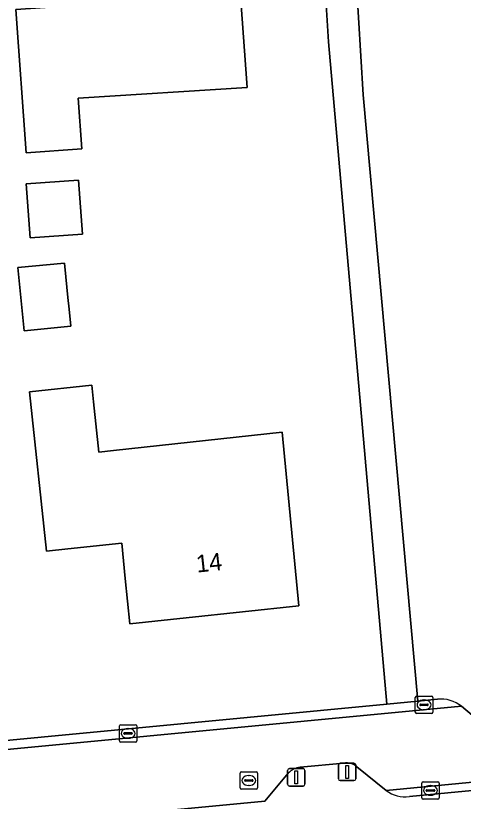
# Model space of a CAD drawing. Extents: x 162661 to 163484, y 380247 to 381230.
# Drawn here: x 163007.21 to 163032.88, y 380282.71 to 380327.82 of the extents above; entities that cross this region are included whole.
import ezdxf

# ---------------------------------------------------------------- set-up
doc = ezdxf.new("R2010")
doc.units = 0
for name, color, linetype in [('IMGEO_Afsluitpaal', 7, 'Continuous'), ('IMGEO_Erf', 7, 'Continuous'), ('IMGEO_Gemengd_bos', 7, 'Continuous'), ('IMGEO_Kolk', 7, 'Continuous'), ('IMGEO_Pand', 7, 'Continuous'), ('IMGEO_Pand_nummerreeks', 7, 'Continuous'), ('IMGEO_Rijbaan_lokaal_gesloten', 7, 'Continuous'), ('IMGEO_Rijbaan_lokaal_open', 7, 'Continuous'), ('IMGEO_Rioolput', 7, 'Continuous'), ('IMGEO_Voetpad_open', 7, 'Continuous')]:
    doc.layers.add(name, color=color, linetype=linetype)

msp = doc.modelspace()

# ---------------------------------------------------------------- linework, layer by layer
at = {"layer": 'IMGEO_Afsluitpaal'}
for p, q in [((163022.906, 380284.583), (163023.696, 380284.583)), ((163023.696, 380284.583), (163022.906, 380284.583)), ((163025.722, 380283.995), (163025.722, 380284.795)), ((163025.722, 380284.795), (163025.722, 380283.995)), ((163025.822, 380284.895), (163026.612, 380284.895)), ((163026.612, 380284.895), (163025.822, 380284.895)), ((163026.712, 380284.795), (163026.712, 380283.995)), ((163026.712, 380283.995), (163026.712, 380284.795)), ((163022.806, 380283.683), (163022.806, 380284.483)), ((163022.806, 380284.483), (163022.806, 380283.683)), ((163023.796, 380284.483), (163023.796, 380283.683)), ((163023.796, 380283.683), (163023.796, 380284.483)), ((163026.612, 380283.895), (163025.822, 380283.895)), ((163025.822, 380283.895), (163026.612, 380283.895)), ((163023.696, 380283.583), (163022.906, 380283.583)), ((163022.906, 380283.583), (163023.696, 380283.583))]:
    msp.add_line(p, q, dxfattribs=at)
for points in [[(163026.142, 380284.77), (163026.292, 380284.77), (163026.292, 380284.02), (163026.142, 380284.02), (163026.142, 380284.77)], [(163023.226, 380284.458), (163023.376, 380284.458), (163023.376, 380283.708), (163023.226, 380283.708), (163023.226, 380284.458)]]:
    msp.add_lwpolyline(points, dxfattribs=at)
for centre, start, end in [((163022.906, 380284.483), 90, 180), ((163022.906, 380284.483), 90, 180), ((163023.696, 380284.483), 0, 90), ((163023.696, 380284.483), 360, 90), ((163025.822, 380284.795), 90, 180), ((163025.822, 380284.795), 90, 180), ((163026.612, 380284.795), 0, 90), ((163026.612, 380284.795), 360, 90), ((163022.906, 380283.683), 180, 270), ((163022.906, 380283.683), 180, 270), ((163023.696, 380283.683), 270, 0), ((163023.696, 380283.683), 270, 0), ((163025.822, 380283.995), 180, 270), ((163025.822, 380283.995), 180, 270), ((163026.612, 380283.995), 270, 0), ((163026.612, 380283.995), 270, 0)]:
    msp.add_arc(centre, 0.1, start, end, dxfattribs=at)
at = {"layer": 'IMGEO_Erf'}
for points in [[(163139.978, 380304.779), (163136.519, 380351.021), (163135.092, 380350.931), (163034.276, 380343.853), (163025.928, 380343.278), (163027.147, 380323.267), (163030.282, 380288.461), (163031.404, 380288.568)], [(163032.785, 380288.167), (163034.368, 380286.84)]]:
    msp.add_lwpolyline(points, dxfattribs=at)
for points in [[(163025.144, 380326.321), (163024.481, 380337.057), (163009.587, 380336.032), (163009.593, 380335.742), (163006.725, 380335.529), (163006.73, 380335.638), (163003.141, 380335.415), (163000, 380335.199), (162936.743, 380330.858), (162941.559, 380279.973), (163028.489, 380288.289)], [(163010.171, 380330.413), (163009.999, 380333.038), (163019.769, 380333.708), (163020.494, 380323.704), (163010.794, 380323.077), (163011.003, 380320.184), (163007.811, 380319.954), (163007.219, 380328.173), (163010.303, 380328.395)], [(163007.817, 380318.159), (163010.814, 380318.375), (163011.037, 380315.276), (163008.041, 380315.06)], [(163007.331, 380313.357), (163010.007, 380313.619), (163010.22, 380311.45), (163010.249, 380311.157), (163010.364, 380309.986), (163007.687, 380309.724)], [(163008.004, 380306.229), (163011.579, 380306.609), (163011.681, 380305.647), (163011.988, 380302.761), (163012.826, 380302.853), (163022.489, 380303.909), (163023.451, 380293.925), (163013.765, 380292.896), (163013.498, 380295.509), (163013.292, 380297.532), (163010.209, 380297.204), (163008.979, 380297.073)]]:
    msp.add_lwpolyline(points, close=True, dxfattribs=at)
msp.add_arc((163031.6, 380286.664), 1.914, 51.7444, 95.8722, dxfattribs=at)
at = {"layer": 'IMGEO_Gemengd_bos'}
for points in [[(163140.672, 380293.543), (163138.153, 380293.364), (163029.791, 380282.976)], [(163026.035, 380284.904), (163023.529, 380284.664)], [(163028.455, 380283.329), (163026.78, 380284.687)], [(163022.836, 380284.315), (163021.508, 380282.709)]]:
    msp.add_lwpolyline(points, dxfattribs=at)
for centre, radius, start, end in [((163023.635, 380283.591), 1.078, 95.6384, 137.8219), ((163026.175, 380283.997), 0.918, 48.7473, 98.7737), ((163029.554, 380284.783), 1.822, 232.9158, 277.4831)]:
    msp.add_arc(centre, radius, start, end, dxfattribs=at)
at = {"layer": 'IMGEO_Kolk'}
for p, q in [((163030.131, 380287.822), (163030.131, 380288.674)), ((163030.206, 380288.748), (163031.058, 380288.748)), ((163031.132, 380288.674), (163031.132, 380287.822)), ((163030.39, 380288.242), (163030.39, 380288.254)), ((163030.828, 380288.205), (163030.43, 380288.205)), ((163030.433, 380288.291), (163030.831, 380288.291)), ((163030.619, 380288.528), (163030.644, 380288.528)), ((163030.874, 380288.254), (163030.874, 380288.242)), ((163031.058, 380287.748), (163030.206, 380287.748)), ((163030.642, 380287.968), (163030.617, 380287.968)), ((163013.157, 380286.181), (163013.157, 380287.033)), ((163013.232, 380287.107), (163014.084, 380287.107)), ((163013.645, 380286.887), (163013.67, 380286.887)), ((163014.158, 380287.033), (163014.158, 380286.181)), ((163013.416, 380286.601), (163013.416, 380286.613)), ((163013.854, 380286.564), (163013.456, 380286.564)), ((163013.459, 380286.65), (163013.857, 380286.65)), ((163013.668, 380286.327), (163013.643, 380286.327)), ((163013.9, 380286.613), (163013.9, 380286.601)), ((163014.084, 380286.107), (163013.232, 380286.107)), ((163030.498, 380282.907), (163030.498, 380283.759)), ((163030.573, 380283.833), (163031.425, 380283.833)), ((163031.499, 380283.759), (163031.499, 380282.907)), ((163030.757, 380283.327), (163030.757, 380283.339)), ((163031.195, 380283.29), (163030.797, 380283.29)), ((163030.8, 380283.376), (163031.198, 380283.376)), ((163030.986, 380283.613), (163031.011, 380283.613)), ((163031.241, 380283.339), (163031.241, 380283.327)), ((163031.425, 380282.833), (163030.573, 380282.833)), ((163031.009, 380283.053), (163030.984, 380283.053))]:
    msp.add_line(p, q, dxfattribs=at)
for points in [[(163030.131, 380287.822), (163030.131, 380288.674)], [(163030.206, 380288.748), (163031.058, 380288.748)], [(163031.132, 380288.674), (163031.132, 380287.822)], [(163031.058, 380287.748), (163030.206, 380287.748)], [(163013.157, 380286.181), (163013.157, 380287.033)], [(163013.232, 380287.107), (163014.084, 380287.107)], [(163014.158, 380287.033), (163014.158, 380286.181)], [(163014.084, 380286.107), (163013.232, 380286.107)], [(163030.498, 380282.907), (163030.498, 380283.759)], [(163030.573, 380283.833), (163031.425, 380283.833)], [(163031.499, 380283.759), (163031.499, 380282.907)], [(163031.425, 380282.833), (163030.573, 380282.833)]]:
    msp.add_lwpolyline(points, dxfattribs=at)
for centre, radius, start, end in [((163030.208, 380288.672), 0.0765, 91.552, 178.448), ((163030.208, 380288.672), 0.0765, 91.552, 178.448), ((163031.056, 380288.672), 0.0765, 1.552, 88.448), ((163031.056, 380288.672), 0.0765, 1.552, 88.448), ((163030.43, 380288.251), 0.0403, 85.8775, 175.7526), ((163030.427, 380288.241), 0.0366, 178.938, 274.7102), ((163030.831, 380288.248), 0.043, 264.8664, 352.4533), ((163030.835, 380288.253), 0.0386, 1.7309, 96.639), ((163030.208, 380287.824), 0.0765, 181.552, 268.448), ((163030.208, 380287.824), 0.0765, 181.552, 268.448), ((163031.056, 380287.824), 0.0765, 271.552, 358.448), ((163031.056, 380287.824), 0.0765, 271.552, 358.448), ((163013.234, 380287.031), 0.0765, 91.552, 178.448), ((163013.234, 380287.031), 0.0765, 91.552, 178.448), ((163014.082, 380287.031), 0.0765, 1.552, 88.448), ((163014.082, 380287.031), 0.0765, 1.552, 88.448), ((163013.456, 380286.61), 0.0403, 85.8775, 175.7526), ((163013.453, 380286.6), 0.0366, 178.938, 274.7102), ((163013.857, 380286.607), 0.043, 264.8664, 352.4533), ((163013.861, 380286.612), 0.0386, 1.7309, 96.639), ((163013.234, 380286.183), 0.0765, 181.552, 268.448), ((163013.234, 380286.183), 0.0765, 181.552, 268.448), ((163014.082, 380286.183), 0.0765, 271.552, 358.448), ((163014.082, 380286.183), 0.0765, 271.552, 358.448), ((163030.575, 380283.757), 0.0765, 91.552, 178.448), ((163030.575, 380283.757), 0.0765, 91.552, 178.448), ((163031.423, 380283.757), 0.0765, 1.552, 88.448), ((163031.423, 380283.757), 0.0765, 1.552, 88.448), ((163030.797, 380283.336), 0.0403, 85.8775, 175.7526), ((163030.794, 380283.326), 0.0366, 178.938, 274.7102), ((163031.198, 380283.333), 0.043, 264.8664, 352.4533), ((163031.202, 380283.338), 0.0386, 1.7309, 96.639), ((163030.575, 380282.909), 0.0765, 181.552, 268.448), ((163030.575, 380282.909), 0.0765, 181.552, 268.448), ((163031.423, 380282.909), 0.0765, 271.552, 358.448), ((163031.423, 380282.909), 0.0765, 271.552, 358.448)]:
    msp.add_arc(centre, radius, start, end, dxfattribs=at)
for centre, major_axis, ratio, start_param, end_param in [((163030.618, 380288.248), (-0.387, 0.002), 0.722429, 4.712389, 7.853982), ((163030.643, 380288.248), (-0.39, 0.002), 0.717154, 1.570796, 4.712389), ((163013.644, 380286.607), (-0.387, 0.002), 0.722429, 4.712389, 7.853982), ((163013.669, 380286.607), (-0.39, 0.002), 0.717154, 1.570796, 4.712389), ((163030.985, 380283.333), (-0.387, 0.002), 0.722429, 4.712389, 7.853982), ((163031.01, 380283.333), (-0.39, 0.002), 0.717154, 1.570796, 4.712389)]:
    msp.add_ellipse(centre, major_axis=major_axis, ratio=ratio, start_param=start_param, end_param=end_param, dxfattribs=at)
at = {"layer": 'IMGEO_Pand'}
for points in [[(163010.171, 380330.413), (163010.303, 380328.395), (163007.219, 380328.173), (163007.811, 380319.954), (163011.003, 380320.184), (163010.794, 380323.077), (163020.494, 380323.704), (163019.769, 380333.708), (163009.999, 380333.038)], [(163007.817, 380318.159), (163008.041, 380315.06), (163011.037, 380315.276), (163010.814, 380318.375)], [(163007.331, 380313.357), (163007.687, 380309.724), (163010.364, 380309.986), (163010.249, 380311.157), (163010.22, 380311.45), (163010.007, 380313.619)], [(163022.489, 380303.909), (163012.826, 380302.853), (163011.988, 380302.761), (163011.681, 380305.647), (163011.579, 380306.609), (163008.004, 380306.229), (163008.979, 380297.073), (163010.209, 380297.204), (163013.292, 380297.532), (163013.498, 380295.509), (163013.765, 380292.896), (163023.451, 380293.925)]]:
    msp.add_lwpolyline(points, close=True, dxfattribs=at)
at = {"layer": 'IMGEO_Rijbaan_lokaal_gesloten'}
for points in [[(163026.78, 380284.687), (163028.455, 380283.329), (163112.592, 380291.447), (163140.62, 380294.079)], [(163034.368, 380286.84), (163032.785, 380288.167), (162941.711, 380279.483), (162940.195, 380274.962), (163021.508, 380282.709)], [(163023.529, 380284.664), (163026.035, 380284.904)], [(163021.508, 380282.709), (163022.836, 380284.315)]]:
    msp.add_lwpolyline(points, dxfattribs=at)
for centre, radius, start, end in [((163023.635, 380283.591), 1.078, 95.6384, 137.8219), ((163026.175, 380283.997), 0.918, 48.7473, 98.7737)]:
    msp.add_arc(centre, radius, start, end, dxfattribs=at)
at = {"layer": 'IMGEO_Rijbaan_lokaal_open'}
for points in [[(163140.62, 380294.079), (163112.592, 380291.447), (163028.455, 380283.329)], [(163029.791, 380282.976), (163138.153, 380293.364)], [(163031.404, 380288.568), (163030.282, 380288.461), (163028.489, 380288.289), (162941.559, 380279.973), (162941.711, 380279.483), (163032.785, 380288.167)], [(163021.508, 380282.709), (162940.195, 380274.962)]]:
    msp.add_lwpolyline(points, dxfattribs=at)
for centre, radius, start, end in [((163031.6, 380286.664), 1.914, 51.7444, 95.8722), ((163029.554, 380284.783), 1.822, 232.9158, 277.4831)]:
    msp.add_arc(centre, radius, start, end, dxfattribs=at)
at = {"layer": 'IMGEO_Rioolput'}
for p, q in [((163020.082, 380283.476), (163020.082, 380284.328)), ((163020.157, 380284.402), (163021.009, 380284.402)), ((163020.57, 380284.182), (163020.595, 380284.182)), ((163021.083, 380284.328), (163021.083, 380283.476)), ((163020.341, 380283.896), (163020.341, 380283.908)), ((163020.779, 380283.859), (163020.381, 380283.859)), ((163020.384, 380283.945), (163020.782, 380283.945)), ((163020.593, 380283.622), (163020.568, 380283.622)), ((163020.825, 380283.908), (163020.825, 380283.896)), ((163021.009, 380283.402), (163020.157, 380283.402))]:
    msp.add_line(p, q, dxfattribs=at)
for points in [[(163020.082, 380283.476), (163020.082, 380284.328)], [(163020.157, 380284.402), (163021.009, 380284.402)], [(163021.083, 380284.328), (163021.083, 380283.476)], [(163021.009, 380283.402), (163020.157, 380283.402)]]:
    msp.add_lwpolyline(points, dxfattribs=at)
for centre, radius, start, end in [((163020.159, 380284.326), 0.0765, 91.552, 178.448), ((163020.159, 380284.326), 0.0765, 91.552, 178.448), ((163021.007, 380284.326), 0.0765, 1.552, 88.448), ((163021.007, 380284.326), 0.0765, 1.552, 88.448), ((163020.381, 380283.905), 0.0403, 85.8775, 175.7526), ((163020.378, 380283.895), 0.0366, 178.938, 274.7102), ((163020.782, 380283.902), 0.043, 264.8664, 352.4533), ((163020.786, 380283.907), 0.0386, 1.7309, 96.639), ((163020.159, 380283.478), 0.0765, 181.552, 268.448), ((163020.159, 380283.478), 0.0765, 181.552, 268.448), ((163021.007, 380283.478), 0.0765, 271.552, 358.448), ((163021.007, 380283.478), 0.0765, 271.552, 358.448)]:
    msp.add_arc(centre, radius, start, end, dxfattribs=at)
for centre, major_axis, ratio, start_param, end_param in [((163020.569, 380283.902), (-0.387, 0.002), 0.722429, 4.712389, 7.853982), ((163020.594, 380283.902), (-0.39, 0.002), 0.717154, 1.570796, 4.712389)]:
    msp.add_ellipse(centre, major_axis=major_axis, ratio=ratio, start_param=start_param, end_param=end_param, dxfattribs=at)
at = {"layer": 'IMGEO_Voetpad_open'}
msp.add_lwpolyline([(163027.147, 380323.267), (163025.928, 380343.278), (163025.83, 380345.117), (163025.56, 380349.347), (163025.172, 380349.33), (163023.757, 380349.23), (163024.397, 380338.853), (163024.481, 380337.057), (163025.144, 380326.321), (163028.489, 380288.289), (163030.282, 380288.461)], close=True, dxfattribs=at)

# ---------------------------------------------------------------- texts
at = {"layer": 'IMGEO_Pand_nummerreeks'}
msp.add_text('14', height=1, rotation=6.0619, dxfattribs=at).set_placement((163017.611, 380295.839))

doc.saveas('drawing.dxf')
